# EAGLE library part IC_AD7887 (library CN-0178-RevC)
2.7 V to 5.25 V, Micropower, 2-Channel, 125 kSPS, 12-Bit ADC
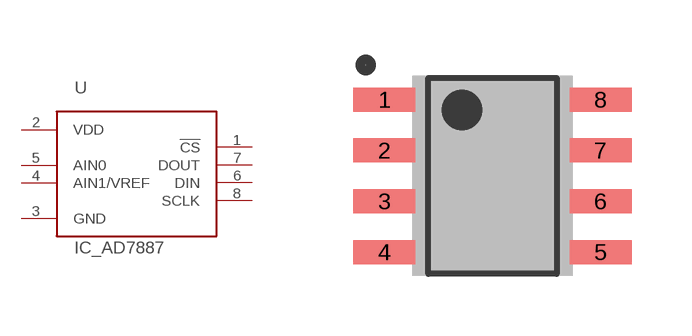
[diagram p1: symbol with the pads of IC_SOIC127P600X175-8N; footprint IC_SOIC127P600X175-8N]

Designator prefix U

## IC_AD7887_SOIC8  [IC_SOIC127P600X175-8N]
1  !CS  pas
2  VDD  pas
3  GND  pas
4  AIN1/VREF  pas
5  AIN0  pas
6  DIN  pas
7  DOUT  pas
8  SCLK  pas

## Footprint IC_SOIC127P600X175-8N (pad centres in mm)
(SOIC-8) 1.27mm pitch; 3.90mm W X 4.90mm L X 1.75mm H body; JEDEC MS-012AA
smd 1.55 x 0.6: 1 -2.7,1.905; 2 -2.7,0.635; 3 -2.7,-0.635; 4 -2.7,-1.905; 5 2.7,-1.905; 6 2.7,-0.635; 7 2.7,0.635; 8 2.7,1.905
